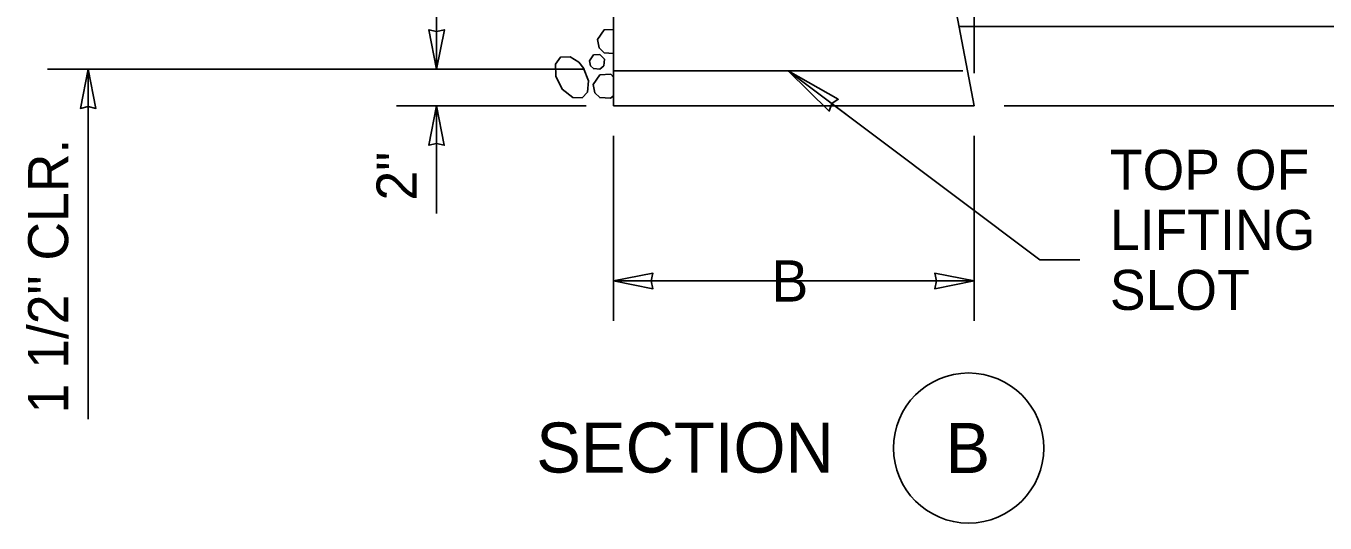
# Model space of a CAD drawing. Extents: x 99862 to 103680, y 99470 to 102076.
# Drawn here: x 102159 to 102678, y 100905 to 101103 of the extents above; entities that cross this region are included whole.
import ezdxf

# ---------------------------------------------------------------- set-up
doc = ezdxf.new("R2010")
doc.units = 0
for name, color, linetype in [('Level 15', 7, 'Continuous'), ('Level 16', 7, 'Continuous'), ('Level 2', 7, 'Continuous'), ('Level 20', 7, 'Continuous'), ('Level 7', 7, 'Continuous'), ('Level 9', 7, 'Continuous')]:
    doc.layers.add(name, color=color, linetype=linetype)

msp = doc.modelspace()

# ---------------------------------------------------------------- linework, layer by layer
at = {"layer": 'Level 15'}
for p, q in [((102538, 101084.63), (102538, 101226.2)), ((102323.37, 101086.27), (102323.37, 101118.27)), ((102168, 101086.27), (102382, 101086.27)), ((102184.23, 101086.27), (102184.23, 100946.27)), ((102463.71, 101085.55), (102564.26, 101009.96)), ((102487.14, 101067.93), (102463.71, 101085.55)), ((102383.03, 101071.55), (102307.36, 101071.55)), ((102323.35, 101071.55), (102323.35, 101028.56)), ((102550, 101071.55), (102844.25, 101071.55)), ((102394, 101059.55), (102394, 100985.55)), ((102538, 101059.55), (102538, 100985.55)), ((102580.19, 101009.98), (102564.19, 101009.98)), ((102538, 101001.55), (102394, 101001.55))]:
    msp.add_line(p, q, dxfattribs=at)
for points in [[(102323.37, 101086.27), (102326.45, 101101.99), (102323.37, 101101.26), (102320.29, 101101.99)], [(102184.23, 101086.27), (102187.32, 101070.54), (102184.23, 101071.27), (102181.15, 101070.54)], [(102463.71, 101085.55), (102483.75, 101074.21), (102481.11, 101072.46), (102480.16, 101069.44)], [(102323.35, 101071.55), (102326.43, 101055.82), (102323.35, 101056.55), (102320.26, 101055.82)], [(102394, 101001.55), (102409.72, 100998.46), (102408.99, 101001.55), (102409.72, 101004.63)], [(102538, 101001.55), (102522.27, 100998.46), (102523, 101001.55), (102522.27, 101004.63)]]:
    msp.add_lwpolyline(points, close=True, dxfattribs=at)
at = {"layer": 'Level 16'}
msp.add_line((102804.93, 101103.31), (102531.69, 101103.31), dxfattribs=at)
at = {"layer": 'Level 2'}
for p, q in [((102533.43, 101085.55), (102394, 101085.55)), ((102538, 101071.55), (102394, 101071.55))]:
    msp.add_line(p, q, dxfattribs=at)
msp.add_lwpolyline([(102394, 101071.55), (102394, 101401.55), (102400, 101407.55), (102468, 101407.55), (102475.12, 101401.65), (102538, 101071.55)], dxfattribs=at)
at = {"layer": 'Level 7'}
for points in [[(102387.56, 101098.05), (102390.25, 101101.88), (102394, 101102.09)], [(102394, 101092.52), (102390.2, 101092.79), (102388.21, 101094.73), (102387.56, 101098.05)], [(102382.01, 101086.64), (102384, 101081.61), (102383.6, 101076.99), (102381.52, 101074.79), (102377.77, 101074.86), (102373.5, 101078.2), (102370.93, 101083.35), (102370.84, 101088.2), (102372.79, 101090.94), (102376.65, 101091.2), (102380.11, 101088.98), (102382.14, 101086.44)], [(102384.4, 101089.59), (102386.01, 101091.88), (102388.59, 101092.03), (102390.38, 101090.17), (102390.12, 101087.57), (102388.53, 101086.25), (102385.98, 101086.43), (102384.79, 101087.59), (102384.4, 101089.59)], [(102385.88, 101080.12), (102388.57, 101083.95), (102392.87, 101084.19), (102394, 101083.02)], [(102394, 101075.58), (102392.77, 101074.56), (102388.53, 101074.86), (102386.53, 101076.8), (102385.89, 101080.12)]]:
    msp.add_lwpolyline(points, dxfattribs=at)
at = {"layer": 'Level 9'}
msp.add_circle((102535.79, 100934.77), 30, dxfattribs=at)

# ---------------------------------------------------------------- texts
at = {"layer": 'Level 15'}
msp.add_text('B', height=16.5, dxfattribs=at).set_placement((102457.06, 100993.3))
at = {"layer": 'Level 20'}
for s, p in [('1 1/2" CLR. ', (102176.23, 100948.55)), ('2"', (102315.36, 101033.68))]:
    msp.add_text(s, height=16, rotation=90, dxfattribs=at).set_placement(p)
for s, height, p in [('TOP OF ', 16, (102592.19, 101037.98)), ('LIFTING ', 16, (102592.19, 101013.98)), ('SLOT', 16, (102592.19, 100989.98)), ('SECTION', 20, (102363.13, 100924.95)), ('B', 20, (102526.55, 100924.77))]:
    msp.add_text(s, height=height, dxfattribs=at).set_placement(p)

doc.saveas('drawing.dxf')
